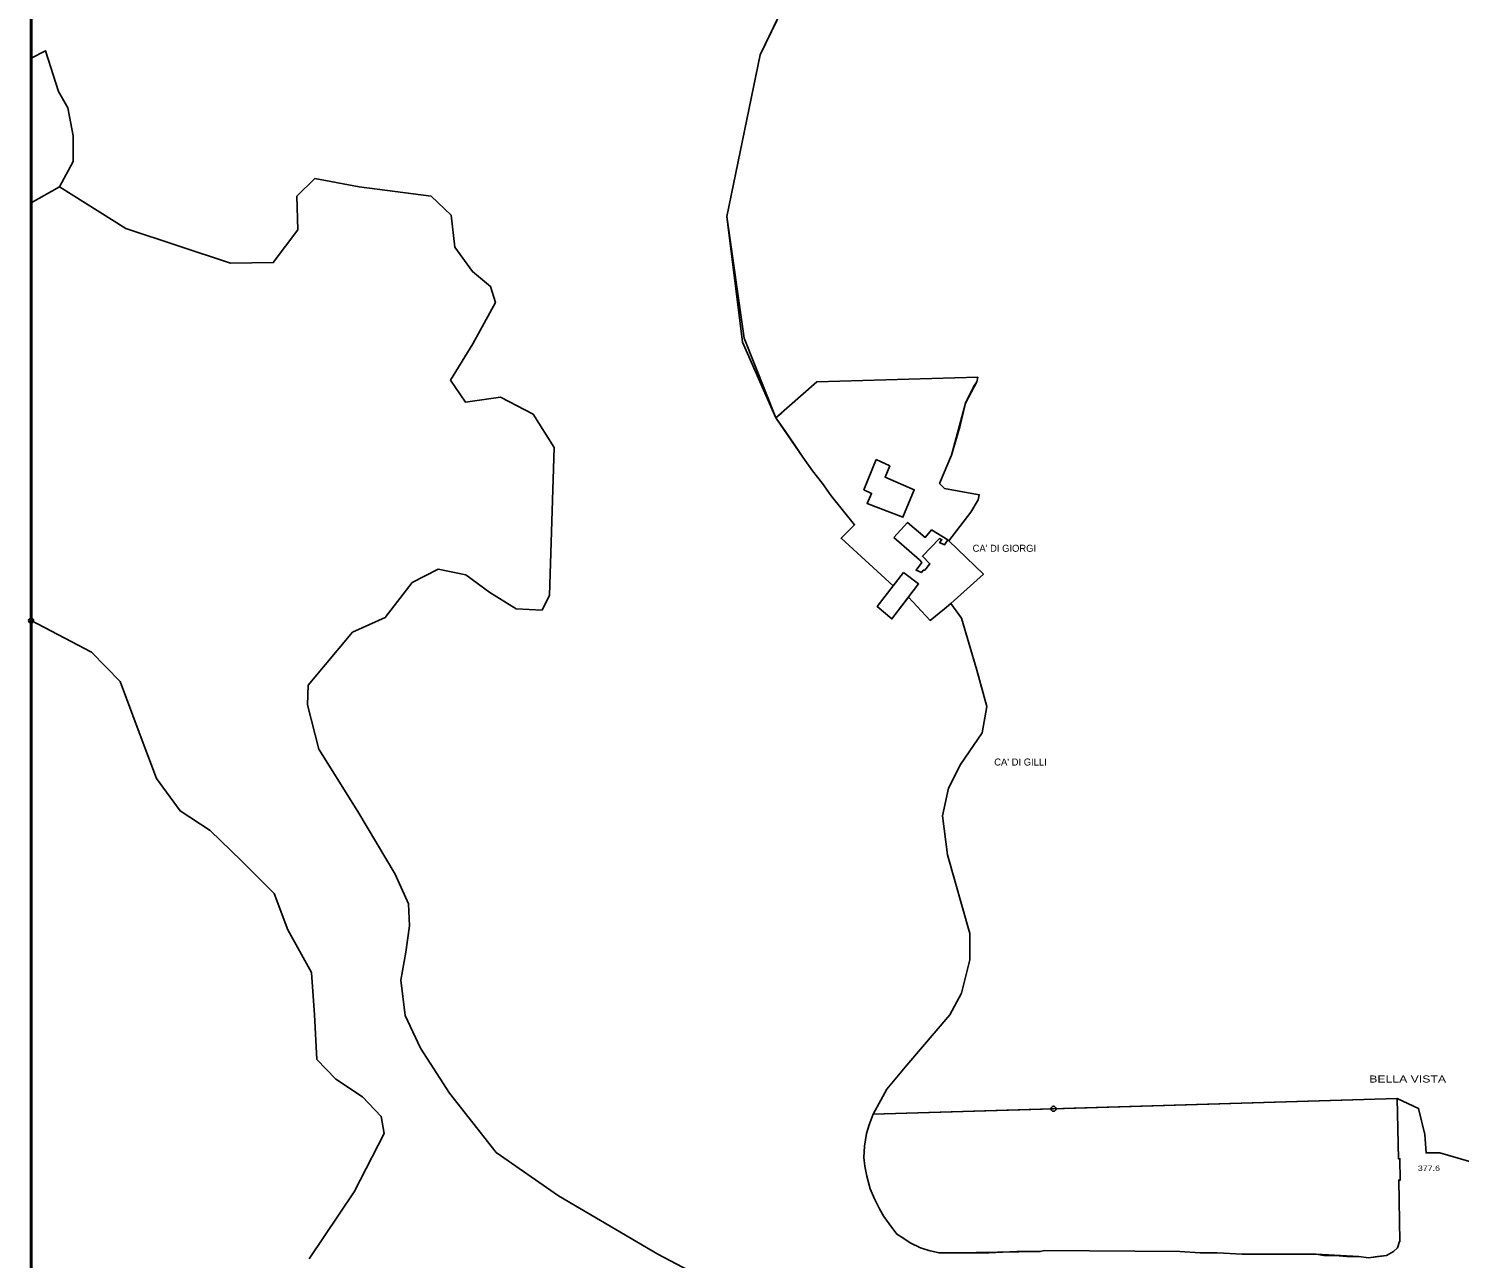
# Model space of a CAD drawing. Extents: x 654952 to 658955, y 890426 to 894481.
# Drawn here: x 657054 to 657624, y 892344 to 892834 of the extents above; entities that cross this region are included whole.
import ezdxf

# ---------------------------------------------------------------- set-up
doc = ezdxf.new("R2010")
doc.units = 0
doc.header["$LTSCALE"] = 4
doc.header["$PDMODE"] = 32
doc.header["$PDSIZE"] = 2
for name, color, linetype, lineweight in [('2', 7, 'Continuous', 25), ('35', 7, 'Continuous', 25), ('36', 7, 'Continuous', 25), ('37', 7, 'Continuous', 25), ('38', 7, 'Continuous', 25), ('60', 7, 'Continuous', 35)]:
    doc.layers.add(name, color=color, linetype=linetype, lineweight=lineweight)
doc.layers.add('58', color=7, linetype='Continuous')

msp = doc.modelspace()

# ---------------------------------------------------------------- linework, layer by layer
at = {"layer": '2'}
for points in [[(657383.01, 892636), (657378.63, 892641.44), (657373.63, 892647.44), (657370.25, 892652.44), (657366.25, 892657.44), (657362.37, 892662.94), (657358.63, 892668.44), (657354.63, 892674.44), (657351.71, 892678.55), (657354.01, 892680.59), (657367.93, 892692.92), (657432.02, 892694.71), (657431.63, 892692.94), (657430.44, 892691.19), (657427.13, 892684.44), (657424.87, 892674.94), (657421.56, 892663.69), (657416.87, 892652.44), (657418.75, 892650.44), (657432.63, 892647.94), (657432.25, 892645.94), (657429.25, 892640.94), (657420.48, 892629.6), (657434.32, 892616.32), (657424.04, 892607.01), (657421.34, 892604.56), (657418.86, 892602.46), (657413.11, 892597.86), (657404.43, 892607.07), (657397.87, 892598.44), (657392, 892603.44), (657398.42, 892611.69)], [(657398.42, 892611.69), (657377.61, 892630.62), (657383.01, 892636)]]:
    msp.add_lwpolyline(points, dxfattribs=at)
for points in [[(657391.63, 892661.94), (657397, 892659.44), (657395.13, 892654.94), (657406.75, 892649.94), (657402.25, 892638.94), (657388, 892644.44), (657389.75, 892648.44), (657386.75, 892649.94)], [(657398.63, 892630.94), (657408.87, 892621.94), (657409.75, 892620.94), (657407.5, 892617.94), (657409.63, 892616.94), (657410.37, 892617.94), (657411, 892617.94), (657413, 892620.44), (657410, 892623.44), (657416.75, 892630.44), (657417.75, 892629.94), (657416.87, 892628.94), (657418.75, 892627.94), (657420.13, 892629.94), (657413.63, 892633.94), (657411.13, 892630.94), (657404.13, 892636.94)], [(657402.5, 892616.94), (657392, 892603.44), (657397.87, 892598.44), (657408.5, 892612.44)]]:
    msp.add_lwpolyline(points, close=True, dxfattribs=at)
at = {"layer": '35'}
msp.add_line((657372.2, 892878.95), (657345.47, 892823.2), dxfattribs=at)
for points in [[(657345.47, 892823.2), (657332.09, 892758.81), (657338.99, 892710.27), (657351.71, 892678.55), (657367.93, 892692.92), (657432.02, 892694.71)], [(657432.02, 892694.71), (657431.63, 892692.94), (657427.13, 892684.44), (657421.56, 892663.69), (657416.87, 892652.44)], [(657416.87, 892652.44), (657418.75, 892650.44), (657432.63, 892647.94)], [(657432.63, 892647.94), (657432.25, 892645.94), (657429.25, 892640.94), (657420.48, 892629.6), (657434.32, 892616.32), (657421.35, 892604.56), (657425.52, 892598.8), (657431.64, 892578.05), (657435.59, 892563.63), (657433.82, 892553.15), (657425.13, 892540.51), (657420.39, 892531.02)], [(657420.39, 892531.02), (657418.02, 892519.96), (657420, 892504.55), (657428.88, 892473.13)], [(657428.88, 892473.13), (657428.88, 892462.65), (657425.53, 892449.41), (657420.98, 892440.71), (657403.85, 892420.74)], [(657403.85, 892420.74), (657395.9, 892411.08), (657390.46, 892401.17), (657599, 892407.44), (657607.54, 892403.45), (657610.01, 892393.05), (657610.51, 892385.78), (657615.95, 892385.78), (657633.78, 892380.66), (657640.7, 892377.37), (657640.2, 892392.38)]]:
    msp.add_lwpolyline(points, dxfattribs=at)
at = {"layer": '36'}
for points in [[(657183.16, 892593.17), (657196.13, 892598.98), (657206.87, 892612.98), (657217.17, 892618.26), (657228.22, 892616), (657237.77, 892608.96), (657248.32, 892602.42), (657258.62, 892601.92), (657261.54, 892607.96), (657263.36, 892666.73), (657254.99, 892680.02), (657242.03, 892686.8), (657228.06, 892684.86), (657222.08, 892693.57), (657231.05, 892708.08), (657240.03, 892724.54), (657238.01, 892730.89), (657230.84, 892736.84), (657223.86, 892746.52), (657222.44, 892759.29), (657214.4, 892766.84), (657185.76, 892770.61), (657168.17, 892773.88), (657160.89, 892766.84), (657161.39, 892753.51), (657151.59, 892740.44), (657134.51, 892740.19), (657092.81, 892754.01), (657066.47, 892770.54), (657055.17, 892764.26), (657055.17, 892597.8), (657079.19, 892585.21), (657090.67, 892573.6), (657098.15, 892553.27), (657105.13, 892534.89), (657114.48, 892521.96), (657126.45, 892514.22), (657138.92, 892502.13), (657151.88, 892489.06), (657157.37, 892474.55)], [(657334.42, 892329.69), (657304.73, 892345.36), (657265.18, 892368.72), (657240.29, 892385.98), (657221.7, 892409.61), (657210.15, 892427.46), (657204.12, 892440.53), (657202.36, 892454.61), (657204.37, 892465.67), (657205.87, 892476.23), (657205.37, 892485.03), (657200.09, 892496.84), (657185.27, 892521.73), (657169.7, 892546.62), (657165.17, 892564.22), (657165.42, 892572.01), (657183.16, 892593.17)], [(657157.37, 892474.55), (657166.85, 892457.61), (657167.94, 892440.78), (657168.94, 892422.93), (657176.48, 892415.14), (657187.03, 892408.1), (657194.57, 892400.31), (657195.75, 892393.42), (657183.78, 892370.19), (657165.83, 892343.58)]]:
    msp.add_lwpolyline(points, dxfattribs=at)
at = {"layer": '37'}
for points in [[(657055.17, 893071.01), (657055.17, 892821.87)], [(657338.35, 892708.74), (657332.09, 892758.81), (657345.47, 892823.2), (657372.2, 892878.95)], [(657055.17, 892821.87), (657060.83, 892824.81), (657066.08, 892808.58), (657069.82, 892802.12), (657071.86, 892790.9), (657071.86, 892780.71), (657066.47, 892770.54), (657092.81, 892754.01), (657134.51, 892740.19), (657151.59, 892740.44), (657161.39, 892753.51), (657160.89, 892766.84), (657168.17, 892773.88), (657185.76, 892770.61), (657214.4, 892766.84), (657222.44, 892759.29), (657223.86, 892746.52), (657230.84, 892736.84), (657238.01, 892730.89), (657240.03, 892724.54), (657231.05, 892708.08), (657222.08, 892693.57), (657228.06, 892684.86), (657242.03, 892686.8), (657254.99, 892680.02), (657263.36, 892666.73), (657261.54, 892607.96), (657258.62, 892601.92), (657248.32, 892602.42), (657237.77, 892608.96), (657228.22, 892616), (657217.17, 892618.26), (657206.87, 892612.98), (657196.13, 892598.98), (657183.16, 892593.17), (657165.42, 892572.01), (657165.17, 892564.22), (657169.7, 892546.62), (657185.27, 892521.73), (657200.09, 892496.84)], [(657373.63, 892647.44), (657370.25, 892652.44), (657366.25, 892657.44), (657362.37, 892662.94), (657351.71, 892678.55), (657338.35, 892708.74)], [(657397.87, 892598.44), (657392, 892603.44), (657398.42, 892611.69), (657377.61, 892630.62), (657383.01, 892636), (657373.63, 892647.44)], [(657420, 892504.55), (657418.02, 892519.96), (657420.39, 892531.02), (657425.13, 892540.51), (657433.82, 892553.15), (657435.59, 892563.63), (657431.64, 892578.05), (657425.52, 892598.8), (657421.35, 892604.56), (657418.86, 892602.46), (657413.11, 892597.86), (657404.43, 892607.07), (657397.87, 892598.44)], [(657165.83, 892343.58), (657183.78, 892370.19), (657195.75, 892393.42), (657194.57, 892400.31), (657187.03, 892408.1), (657176.48, 892415.14), (657168.94, 892422.93), (657167.94, 892440.78), (657166.85, 892457.61), (657157.37, 892474.55), (657151.88, 892489.06), (657138.92, 892502.13), (657126.45, 892514.22), (657114.48, 892521.96), (657105.13, 892534.89), (657098.15, 892553.27), (657090.67, 892573.6), (657079.19, 892585.21), (657055.17, 892597.8)], [(657403.85, 892420.74), (657420.98, 892440.71), (657425.53, 892449.41), (657428.88, 892462.65), (657428.88, 892473.13), (657420, 892504.55)], [(657200.09, 892496.84), (657205.37, 892485.03), (657205.87, 892476.23), (657204.37, 892465.67), (657202.36, 892454.61), (657204.12, 892440.53), (657210.15, 892427.46), (657221.7, 892409.61), (657240.29, 892385.98), (657265.18, 892368.72), (657304.73, 892345.36), (657334.42, 892329.69), (657356.62, 892323.38), (657372.19, 892314.83), (657385.36, 892308.86), (657393.84, 892303.53), (657401.84, 892302.26), (657408.87, 892306.53), (657415.15, 892316.34), (657420.77, 892321.44), (657432.24, 892326.27), (657444.35, 892326.94)], [(657390.46, 892401.17), (657395.9, 892411.08), (657403.85, 892420.74)], [(657642.61, 892283.53), (657641.27, 892297.38), (657641.13, 892322.31), (657641.13, 892364.6), (657640.7, 892377.37), (657633.78, 892380.66), (657615.95, 892385.78), (657610.51, 892385.78), (657610.01, 892393.05), (657607.54, 892403.45), (657599, 892407.44), (657599.5, 892383.44)], [(657456.87, 892346.44), (657422.87, 892345.94), (657416.63, 892345.94), (657412.5, 892346.94), (657409.25, 892347.94), (657405.13, 892349.94), (657402.25, 892351.94), (657399.87, 892353.44), (657396.75, 892357.44), (657394.63, 892360.44), (657392.87, 892363.44), (657390.87, 892367.44), (657389.25, 892371.44), (657387.87, 892376.44), (657387.13, 892380.44), (657386.75, 892383.94), (657387, 892388.44), (657387.75, 892393.44), (657388.87, 892396.94), (657390.46, 892401.17)], [(657599.5, 892383.44), (657600.13, 892383.44), (657600.25, 892374.94), (657599.63, 892374.94), (657600.13, 892350.44), (657599.88, 892350.44), (657599.13, 892347.94), (657597.5, 892346.44), (657594.75, 892344.94), (657593.78, 892344.8), (657587.63, 892343.94), (657583.75, 892344.44), (657566.75, 892345.44), (657537.37, 892345.44), (657527.37, 892345.94), (657520.63, 892345.94), (657512.5, 892346.44), (657458.63, 892346.94), (657456.87, 892346.44)]]:
    msp.add_lwpolyline(points, dxfattribs=at)
msp.add_point((657055.17, 892597.8), dxfattribs=at)
at = {"layer": '38'}
for points in [[(657462.19, 892403.32), (657599, 892407.44), (657599.5, 892383.44), (657600.13, 892383.44), (657600.25, 892374.94), (657599.63, 892374.94), (657600.13, 892350.44), (657599.87, 892350.44)], [(657458.62, 892346.94), (657456.87, 892346.44), (657447.63, 892346.44), (657436.5, 892345.94), (657422.87, 892345.94), (657416.63, 892345.94), (657412.5, 892346.94), (657409.25, 892347.94), (657405.13, 892349.94), (657402.25, 892351.94), (657399.87, 892353.44), (657396.75, 892357.44), (657394.63, 892360.44), (657392.87, 892363.44), (657390.87, 892367.44), (657389.25, 892371.44), (657387.87, 892376.44), (657387.13, 892380.44), (657386.75, 892383.94), (657387, 892388.44), (657387.75, 892393.44), (657388.87, 892396.94), (657390.46, 892401.17), (657462.19, 892403.32)], [(657599.88, 892350.44), (657599.13, 892347.94), (657597.5, 892346.44), (657594.75, 892344.94), (657591.25, 892344.44), (657587.63, 892343.94), (657583.75, 892344.44), (657579, 892344.44), (657574.37, 892344.94), (657569.87, 892344.94), (657566.75, 892345.44), (657562.75, 892345.44), (657557.75, 892345.44), (657550.5, 892345.44), (657537.37, 892345.44), (657527.37, 892345.94), (657520.63, 892345.94), (657512.5, 892346.44), (657458.63, 892346.94), (657458.62, 892346.94)]]:
    msp.add_lwpolyline(points, dxfattribs=at)
msp.add_point((657462.19, 892403.32), dxfattribs=at)
at = {"layer": '60', "lineweight": 40}
msp.add_lwpolyline([(657055.17, 894480.74), (658955.28, 894480.74), (658955.28, 890425.88), (657055.17, 890425.88)], close=True, dxfattribs=at)

# ---------------------------------------------------------------- texts
at = {"layer": '58'}
for s, p in [("CA' DI GIORGI", (657429.99, 892625.21)), ("CA' DI GILLI", (657438.59, 892540.06))]:
    msp.add_text(s, height=2.801, dxfattribs=at).set_placement(p)
for s, height, width, p in [('  BELLA VISTA', 2.801, 1.3, (657585.18, 892413.79)), ('377.6', 2.102, 1.25, (657607.26, 892378.61))]:
    msp.add_text(s, height=height, dxfattribs=dict(at, width=width)).set_placement(p)

doc.saveas('drawing.dxf')
